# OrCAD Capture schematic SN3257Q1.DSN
size C
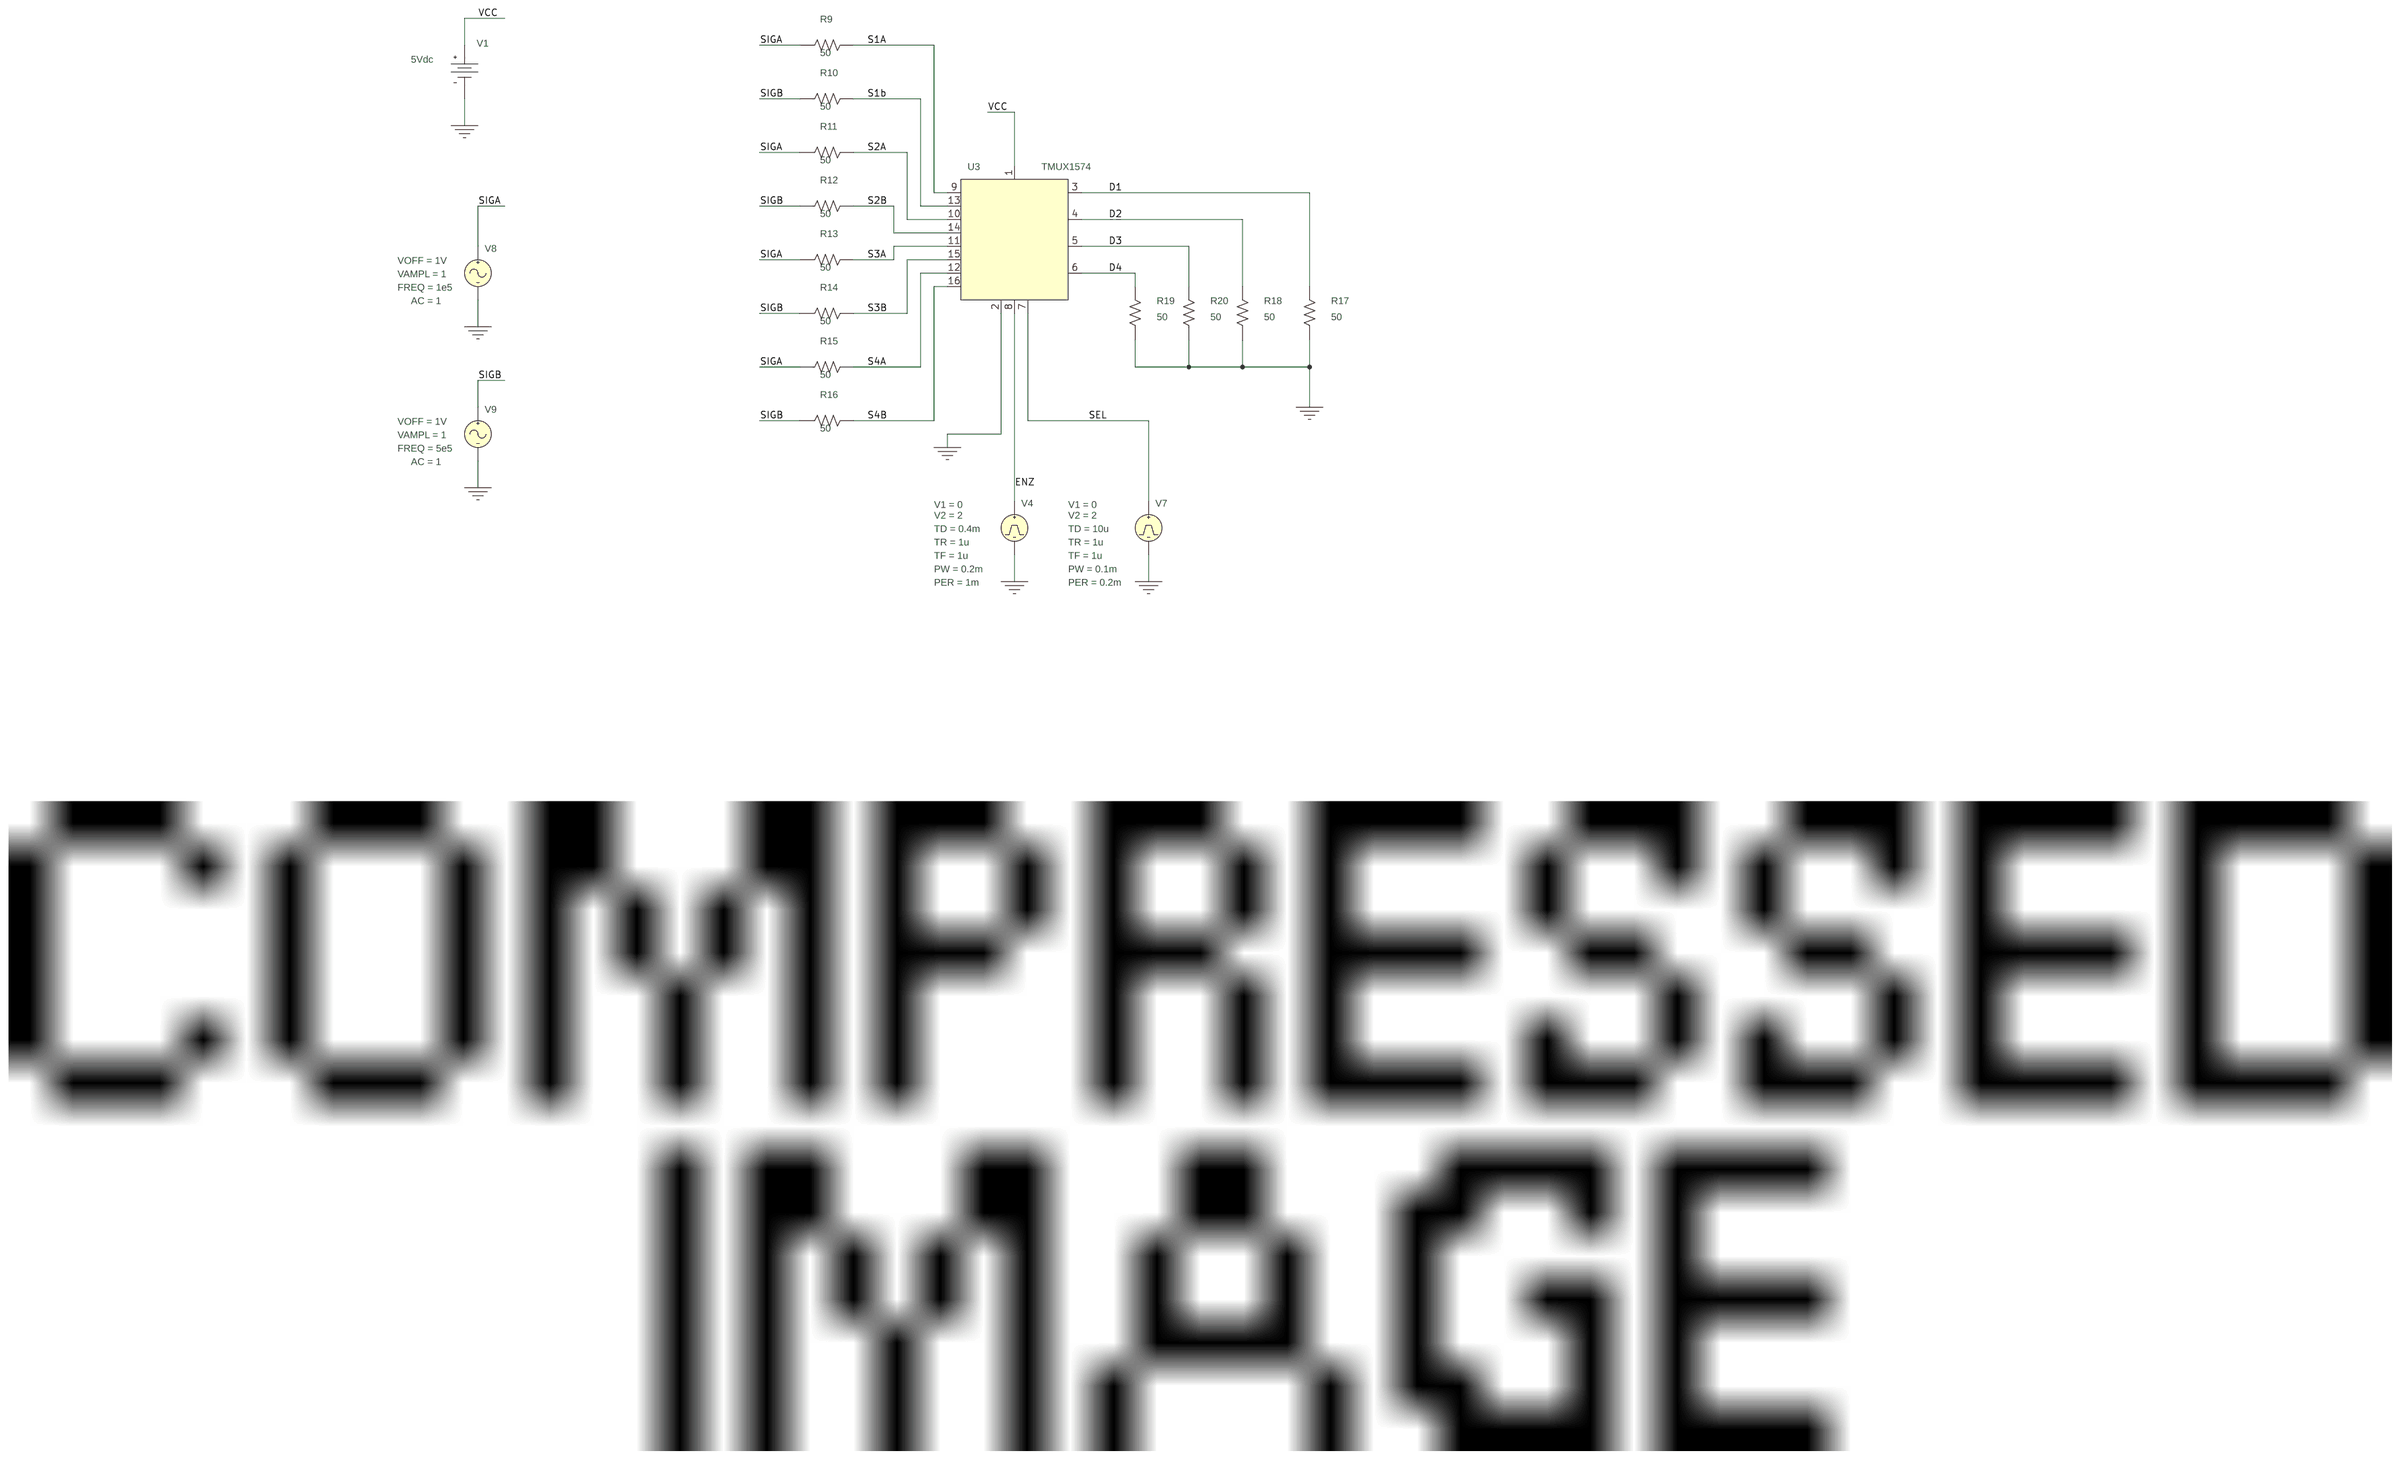
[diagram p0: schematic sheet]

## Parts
R9  50  [AX/RC05]
R10  50  [AX/RC05]
R11  50  [AX/RC05]
R12  50  [AX/RC05]
R13  50  [AX/RC05]
R14  50  [AX/RC05]
R15  50  [AX/RC05]
R16  50  [AX/RC05]
R17  50  [AX/RC05]
R18  50  [AX/RC05]
R19  50  [AX/RC05]
R20  50  [AX/RC05]
U3  TMUX1574
V1  VDC
V4  VPULSE
V7  VPULSE
V8  VSIN
V9  VSIN

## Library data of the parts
R9-R20 = R
U3 = TMUX1574
V1 = VDC: DC: 5Vdc
V4 = VPULSE: PER: 1m; PW: 0.2m; TD: 0.4m; TF: 1u; TR: 1u; V1: 0; V2: 2
V7 = VPULSE: PER: 0.2m; PW: 0.1m; TD: 10u; TF: 1u; TR: 1u; V1: 0; V2: 2
V8 = VSIN: AC: 1; FREQ: 1e5; VAMPL: 1; VOFF: 1V
V9 = VSIN: AC: 1; FREQ: 5e5; VAMPL: 1; VOFF: 1V

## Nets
VCC: U3.1(VCC) V1.0(+)
0: R17.1 R18.1 R19.1 R20.1 U3.2(GND) V1.1(-) V4.2(-) V7.2(-) V8.2(-) V9.2(-)
D1: R17.2 U3.3(D1)
D2: R18.2 U3.4(D2)
D3: R20.2 U3.5(D3)
D4: R19.2 U3.6(D4)
ENZ: U3.8(ENZ) V4.1(+)
S1A: R9.2 U3.9(S1A)
S1b: R10.2 U3.13(S1B)
S2A: R11.2 U3.10(S2A)
S2B: R12.2 U3.14(S2B)
S3A: R13.2 U3.11(S3A)
S3B: R14.2 U3.15(S3B)
S4A: R15.2 U3.12(S4A)
S4B: R16.2 U3.16(S4B)
SEL: U3.7(SEL) V7.1(+)
SIGA: R9.1 R11.1 R13.1 R15.1 V8.1(+)
SIGB: R10.1 R12.1 R14.1 R16.1 V9.1(+)
